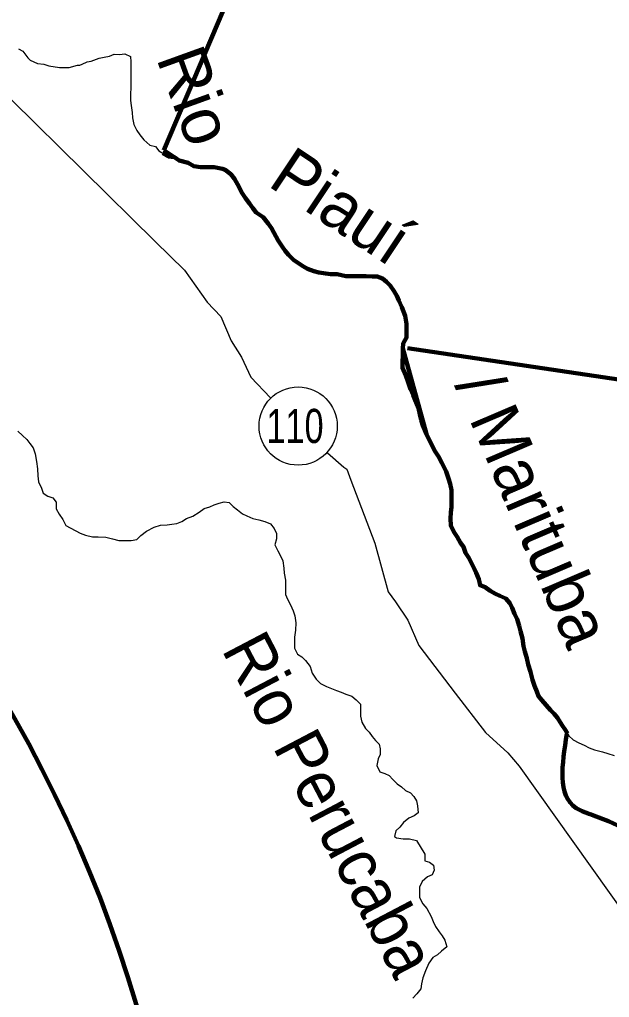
# Model space of a CAD drawing. Extents: x 553962 to 842807, y 8883888 to 9032388.
# Drawn here: x 761992 to 768046, y 8905805 to 8915841 of the extents above; entities that cross this region are included whole.
import ezdxf
from ezdxf.enums import TextEntityAlignment as Align

# ---------------------------------------------------------------- set-up
doc = ezdxf.new("R2010")
doc.units = 0
doc.header["$LTSCALE"] = 20
doc.linetypes.add('MEDIUM_DASHED', pattern=[4.5, 3, -1.5])
for name, color, linetype, lineweight in [('10', 7, 'MEDIUM_DASHED', 60), ('12', 7, 'Continuous', 25), ('24', 7, 'Continuous', 25), ('48', 7, 'Continuous', 25), ('9', 7, 'Continuous', 90)]:
    doc.layers.add(name, color=color, linetype=linetype, lineweight=lineweight)
doc.layers.add('49', color=7, linetype='Continuous')

msp = doc.modelspace()

# ---------------------------------------------------------------- linework, layer by layer
at = {"layer": '10'}
msp.add_open_spline([(780116.15, 8904162.17), (779769.39, 8904177.94), (779422.62, 8904193.71), (779075.85, 8904209.48), (778695.9, 8904226.76), (778318.12, 8904159.82), (777940.98, 8904091.2), (777595.96, 8904028.42), (777262.06, 8903937.23), (776924.32, 8903854.63), (776803.35, 8903825.05), (776686.76, 8903750.37), (776569.67, 8903736.35), (776304.49, 8903704.6), (776099.47, 8903983.3), (775884.02, 8904233.14), (775776.35, 8904358), (775709.21, 8904488.31), (775694.87, 8904611.65), (775670.8, 8904818.6), (776050.43, 8904994.8), (776049.52, 8905226.73), (776047.68, 8905694.49), (775846.84, 8906171.82), (775860.37, 8906646.14), (775878.92, 8907296.23), (776043.6, 8907946.81), (776074.4, 8908597.03), (776108.2, 8909310.28), (775454.34, 8910013.78), (775625.18, 8910702.49), (775746.81, 8911192.83), (776625.71, 8911182.14), (776830.99, 8911648.76), (777030.16, 8912101.51), (777228.07, 8912557.13), (777420.65, 8913014.06), (777556.61, 8913336.63), (777687.59, 8913670.84), (777822.58, 8913983.99), (777919.56, 8914208.95), (778290.17, 8914361.17), (778319.09, 8914551.75), (778353.93, 8914781.35), (778054.25, 8915076.53), (777751.66, 8915261.46), (777515.32, 8915405.89), (777278.58, 8915289.12), (777042.36, 8915285.12), (776916.2, 8915282.98), (776790.12, 8915252.32), (776664.07, 8915261.46), (776484.73, 8915274.46), (776355.68, 8915449.78), (776238.49, 8915592.66), (776104.72, 8915755.73), (776352.41, 8916067), (776214.85, 8916207.73), (776079, 8916346.72), (775768.59, 8916238.74), (775623.77, 8916349.67), (775431.02, 8916497.32), (775387.06, 8916881.69), (775127.26, 8916988.41), (774292.14, 8917331.46), (773439.49, 8917458.06), (772578.86, 8917506.53), (772178.58, 8917529.08), (771773.41, 8917358), (771373.05, 8917411.91), (771257.49, 8917427.47), (771157.31, 8917493.95), (771065.69, 8917577.51), (770748.62, 8917866.67), (770887.06, 8918430.92), (770592.83, 8918689.38), (770430.57, 8918831.91), (770160.08, 8918846.97), (770001.75, 8918996.92), (769746.9, 8919238.26), (769557.21, 8919552.57), (769292.45, 8919801.25), (768866.21, 8920201.59), (768426.67, 8920562.04), (767897.5, 8920818.5), (767600.29, 8920962.53), (767240.04, 8920922.04), (766928.13, 8920842.15), (766587.97, 8920755.03), (766267.79, 8920606.43), (765982.4, 8920369.02), (765805.03, 8920221.47), (765830.93, 8919932.03), (765651.39, 8919801.25), (765249.74, 8919508.69), (764806.41, 8919315.79), (764351.02, 8919115.2), (764017.01, 8918968.08), (763624.43, 8918749.48), (763310.71, 8918831.32)], degree=3, dxfattribs=at)
at = {"layer": '12'}
for points in [[(761912.03, 8915013.75), (763384.05, 8913564.31), (763683.53, 8913268.31), (763916.67, 8912941.85), (764058.77, 8912793.86), (764164.83, 8912544.06), (764271.19, 8912375.76), (764367.23, 8912171.82), (764567.18, 8911957.98)], [(765153.77, 8911394.22), (765321.57, 8911248.03), (765352.06, 8911227.6), (765392.4, 8911115.45), (765639.64, 8910468.05), (765775.35, 8909968.58), (765851.39, 8909866.55)], [(765851.39, 8909866.55), (765978.06, 8909677.84), (766089.18, 8909417.84), (766464.36, 8908928.11), (766773.63, 8908525.11), (767002.1, 8908315.83), (767118.77, 8908178.08), (769146.05, 8905336.93), (769196.75, 8905270.62), (769216.73, 8905163.6), (769289.6, 8904200.68), (769495.6, 8903420.91), (769590.37, 8902870.57), (769609.85, 8902626.02), (769609.02, 8902401.88), (769588.18, 8902274.57), (769536.07, 8901958.83), (769498.71, 8901495.33), (769413.01, 8898973.91), (769458.58, 8898897.42), (769509.37, 8898856.57), (769545.34, 8898826.96)]]:
    msp.add_lwpolyline(points, dxfattribs=at)
at = {"layer": '24'}
for points in [[(761981.19, 8915541.37), (762026.79, 8915515.6), (762075.9, 8915448.89), (762100.99, 8915423.78), (762176.25, 8915390.29)], [(762176.25, 8915390.29), (762243.15, 8915381.92), (762293.32, 8915365.17), (762402.03, 8915348.43), (762502.38, 8915348.43), (762586, 8915373.54), (762611.09, 8915373.54), (762636.17, 8915381.92), (762686.35, 8915407.03), (762728.16, 8915415.4), (762809.57, 8915444.36), (762860.5, 8915454.22), (762916.51, 8915464.05), (762962.43, 8915484.13), (763018.37, 8915483.77), (763074.35, 8915488.51), (763130.12, 8915462.68), (763134.82, 8915406.62), (763134.44, 8915350.59), (763134.05, 8915294.56), (763133.67, 8915238.53), (763133.11, 8915157.03), (763132.44, 8915060.25), (763132.09, 8915009.32), (763136.83, 8914958.35), (763146.51, 8914886.97), (763151.21, 8914830.91), (763166.01, 8914764.59), (763196.11, 8914703.27), (763226.31, 8914657.24), (763266.65, 8914606.04), (763330.23, 8914553.1), (763388.25, 8914539.04), (763422.22, 8914494.49), (763522.56, 8914435.89), (763581.1, 8914427.52), (763631.27, 8914394.03)], [(763631.27, 8914394.03), (763723.26, 8914368.91), (763781.79, 8914335.43), (763848.69, 8914327.05), (763898.86, 8914327.05), (763990.85, 8914327.05), (764074.47, 8914310.31), (764103.76, 8914300.13), (764159.39, 8914253.93), (764199.76, 8914207.83), (764244.94, 8914120.94), (764270.02, 8914069.84), (764310.29, 8914008.46), (764350.59, 8913952.17), (764385.88, 8913906.1), (764421.17, 8913860.02), (764492.05, 8913813.73), (764542.46, 8913747.18), (764577.74, 8913701.11), (764602.86, 8913655.1), (764648.07, 8913573.31), (764688.34, 8913511.93), (764718.54, 8913465.89), (764753.86, 8913424.91), (764804.37, 8913373.65), (764860.07, 8913337.64), (764905.63, 8913306.78), (764946.93, 8913282.3), (765012.12, 8913260.25), (765062.88, 8913244.65), (765134.01, 8913234), (765184.84, 8913228.58), (765250.95, 8913228.16), (765342.36, 8913207.2), (765403.39, 8913206.8), (765464.42, 8913206.41), (765550.89, 8913205.86), (765611.92, 8913205.47), (765662.78, 8913205.14), (765718.58, 8913184.41), (765759.02, 8913148.49), (765794.38, 8913112.61), (765834.68, 8913056.32), (765864.85, 8913005.18), (765884.88, 8912959.21), (765914.9, 8912887.7), (765949.91, 8912800.88), (765964.61, 8912719.29), (765964.01, 8912632.7), (765963.63, 8912576.67), (765927.6, 8912515.77), (765927.18, 8912454.65), (765926.8, 8912398.62), (765921.19, 8912322.25), (765920.8, 8912266.22), (765955.88, 8912189.58), (765980.82, 8912118.11), (766005.76, 8912046.64), (766030.77, 8911985.35), (766050.76, 8911934.28), (766085.8, 8911852.56), (766100.6, 8911786.24), (766115.48, 8911730.11), (766130.35, 8911673.98), (766170.44, 8911587.13)], [(761976.33, 8911618.35), (762021.79, 8911572.22), (762067.28, 8911531.17), (762097.52, 8911490.23), (762132.81, 8911444.16), (762152.73, 8911382.9), (762167.46, 8911306.4), (762177.11, 8911229.93), (762181.7, 8911158.59), (762186.37, 8911097.43), (762216.43, 8911031.02), (762236.42, 8910979.95), (762281.99, 8910949.1), (762332.74, 8910933.49), (762368.03, 8910887.42), (762367.57, 8910821.2), (762397.7, 8910764.98), (762438.01, 8910708.69), (762468.1, 8910647.37), (762615.07, 8910570.02), (762670.87, 8910549.28), (762741.97, 8910533.54), (762797.92, 8910533.19), (762879.26, 8910527.57), (762945.27, 8910511.87), (763011.28, 8910496.16), (763062.14, 8910495.83), (763138.43, 8910495.34), (763194.45, 8910505.17), (763235.42, 8910545.66), (763296.76, 8910591.11), (763373.33, 8910631.37), (763439.59, 8910651.32), (763505.74, 8910655.99), (763556.64, 8910660.76), (763607.57, 8910670.62), (763658.57, 8910690.67), (763704.55, 8910720.94), (763770.84, 8910745.98), (763837.24, 8910786.31), (763888.34, 8910821.64), (763944.43, 8910841.65), (763990.34, 8910861.73), (764041.31, 8910876.69), (764092.27, 8910891.64), (764143.1, 8910886.22), (764183.5, 8910845.21), (764229.03, 8910809.26), (764279.61, 8910768.19), (764325.25, 8910747.52), (764386.1, 8910721.66), (764447.03, 8910705.99), (764507.96, 8910690.31), (764568.81, 8910664.46), (764604.1, 8910618.38), (764629.18, 8910567.28), (764628.79, 8910511.25), (764613.11, 8910450.23), (764643.21, 8910388.91), (764668.32, 8910342.9)], [(766170.44, 8911587.13), (766190.47, 8911541.16), (766215.55, 8911490.06), (766250.66, 8911418.52), (766290.93, 8911357.14), (766326.08, 8911290.69), (766371.25, 8911203.8), (766396.19, 8911132.33), (766411.07, 8911076.2), (766425.87, 8911009.89), (766425.45, 8910948.76), (766425.06, 8910892.73), (766424.71, 8910841.8), (766419.21, 8910780.71), (766413.7, 8910719.62), (766418.3, 8910648.27), (766448.36, 8910581.86), (766483.61, 8910530.7), (766518.79, 8910469.34), (766549.02, 8910428.4), (766568.95, 8910367.14), (766604.2, 8910315.98), (766634.29, 8910254.66), (766659.41, 8910208.65), (766679.44, 8910162.68), (766704.41, 8910096.3), (766719.25, 8910035.08), (766769.97, 8910014.38), (766820.58, 8909978.4), (766876.32, 8909947.48), (766921.95, 8909926.81), (766982.81, 8909900.95), (767023.15, 8909849.75), (767048.26, 8909803.75), (767073.27, 8909742.46), (767098.31, 8909686.27), (767118.2, 8909619.92)], [(764668.32, 8910342.9), (764693.37, 8910286.71), (764703.02, 8910210.24), (764707.75, 8910159.27), (764722.52, 8910087.86), (764722.17, 8910036.93), (764721.5, 8909940.15), (764741.53, 8909894.18), (764771.63, 8909832.86), (764801.72, 8909771.54), (764816.63, 8909720.5), (764826.31, 8909649.13), (764825.79, 8909572.72), (764815.12, 8909501.48), (764814.74, 8909445.45), (764814.35, 8909389.42), (764844.45, 8909328.1), (764890.05, 8909302.34), (764925.37, 8909261.36), (764975.81, 8909199.91), (764995.7, 8909133.56), (765035.96, 8909072.18), (765081.42, 8909026.04)], [(767118.2, 8909619.92), (767133.08, 8909563.79), (767152.89, 8909487.26), (767162.54, 8909410.79), (767177.41, 8909354.66), (767197.3, 8909288.31), (767212.1, 8909222), (767237.01, 8909145.43), (767256.79, 8909063.8), (767276.72, 8909002.55), (767301.76, 8908946.35), (767316.67, 8908895.32), (767351.99, 8908854.34), (767397.41, 8908803.11), (767442.84, 8908751.88), (767478.19, 8908716), (767513.51, 8908675.02), (767558.8, 8908603.41), (767594.01, 8908547.16), (767629.23, 8908490.9), (767674.72, 8908449.86), (767730.46, 8908418.94), (767786.23, 8908393.11), (767836.91, 8908367.31), (767892.72, 8908346.58), (767973.96, 8908325.68), (768029.8, 8908310.04), (768095.77, 8908289.25)], [(765081.42, 8909026.04), (765142.24, 8908995.09), (765192.96, 8908974.39), (765243.68, 8908953.68), (765294.44, 8908938.08), (765340.07, 8908917.41), (765400.96, 8908896.64), (765446.49, 8908860.69), (765491.95, 8908814.56), (765491.56, 8908758.53), (765491.11, 8908692.31), (765505.95, 8908631.09), (765541.09, 8908564.64), (765581.53, 8908528.73), (765611.74, 8908482.69), (765647.06, 8908441.71), (765682.41, 8908405.83), (765692.24, 8908354.83), (765691.85, 8908298.8), (765671.19, 8908253.08), (765660.56, 8908186.93), (765690.62, 8908120.52), (765741.38, 8908104.91), (765787.01, 8908084.24), (765822.33, 8908043.27), (765867.79, 8907997.13), (765913.36, 8907966.27), (765953.8, 8907930.36), (766004.48, 8907904.56), (766039.84, 8907868.68), (766064.95, 8907822.67), (766074.78, 8907771.67), (766084.46, 8907700.3), (766043.56, 8907670), (765987.44, 8907644.89), (765931.18, 8907599.4), (765895.26, 8907553.79), (765854.29, 8907513.3), (765838.65, 8907457.37), (765862.02, 8907442.53)], [(765862.02, 8907442.53), (765930.18, 8907431.33), (765994.11, 8907432.7), (766065.21, 8907416.96), (766150.69, 8907273.79), (766150.24, 8907207.57), (766200.99, 8907191.96), (766241.47, 8907161.14), (766246.21, 8907110.17), (766225.55, 8907064.46), (766179.63, 8907044.38), (766123.34, 8906993.8), (766097.52, 8906937.93), (766097.17, 8906887), (766096.79, 8906830.97), (766131.93, 8906764.52), (766172.31, 8906718.42), (766217.52, 8906636.62), (766237.51, 8906585.56), (766262.59, 8906534.46), (766297.81, 8906478.2), (766328.04, 8906437.26), (766358.24, 8906391.22), (766378.13, 8906324.87), (766321.87, 8906279.39), (766280.94, 8906243.99), (766234.96, 8906213.72), (766193.88, 8906157.95), (766157.72, 8906076.68), (766131.8, 8906005.54), (766116.12, 8905944.51), (766110.69, 8905893.61), (766069.65, 8905842.93), (766028.65, 8905797.35)]]:
    msp.add_lwpolyline(points, dxfattribs=at)
at = {"layer": '48'}
msp.add_circle((764851.33, 8911668.94), 401.28, dxfattribs=at)
at = {"layer": '9'}
for p, q in [((763631.27, 8914394.03), (763472.95, 8914499.71)), ((767609.5, 8908510.77), (767615.52, 8908512.81))]:
    msp.add_line(p, q, dxfattribs=at)
for points in [[(763472.95, 8914499.71), (765229.79, 8918639.75), (764179.45, 8921366.33), (762373.1, 8922620.98), (762522.62, 8923380.92), (762953.67, 8929651.11), (762956.16, 8929646.55)], [(765974.49, 8912469.58), (771548.77, 8911642.28), (776566.81, 8913518.43), (780614.12, 8917160.13), (782189.61, 8916587.3), (785656.16, 8919415.95), (791912.02, 8922868.02)], [(763463.71, 8914470.26), (763522.56, 8914435.89), (763581.1, 8914427.52), (763631.27, 8914394.03)], [(763463.71, 8914470.26), (763522.56, 8914435.89), (763581.1, 8914427.52), (763631.27, 8914394.03)], [(763631.27, 8914394.03), (763723.26, 8914368.91), (763781.79, 8914335.43), (763848.69, 8914327.05), (763898.86, 8914327.05), (763990.85, 8914327.05), (764074.47, 8914310.31), (764103.76, 8914300.13), (764159.39, 8914253.93), (764199.76, 8914207.83), (764244.94, 8914120.94), (764270.02, 8914069.84), (764310.29, 8914008.46), (764350.59, 8913952.17), (764385.88, 8913906.1), (764421.17, 8913860.02), (764492.05, 8913813.73), (764542.46, 8913747.18), (764577.74, 8913701.11), (764602.86, 8913655.1), (764648.07, 8913573.31), (764688.34, 8913511.93), (764718.54, 8913465.89), (764753.86, 8913424.91), (764804.37, 8913373.65), (764860.07, 8913337.64), (764905.63, 8913306.78), (764946.93, 8913282.3), (765012.12, 8913260.25), (765062.88, 8913244.65), (765134.01, 8913234), (765184.84, 8913228.58), (765250.95, 8913228.16), (765342.36, 8913207.2), (765403.39, 8913206.8), (765464.42, 8913206.41), (765550.89, 8913205.86), (765611.92, 8913205.47), (765662.78, 8913205.14), (765718.58, 8913184.41), (765759.02, 8913148.49), (765794.38, 8913112.61), (765834.68, 8913056.32), (765864.85, 8913005.18), (765884.88, 8912959.21), (765914.9, 8912887.7), (765949.91, 8912800.88), (765964.61, 8912719.29), (765964.01, 8912632.7), (765963.63, 8912576.67), (765927.6, 8912515.77), (765927.26, 8912465.57)], [(763631.27, 8914394.03), (763723.26, 8914368.91), (763781.79, 8914335.43), (763848.69, 8914327.05), (763898.86, 8914327.05), (763990.85, 8914327.05), (764074.47, 8914310.31), (764103.76, 8914300.13), (764159.39, 8914253.93), (764199.76, 8914207.83), (764244.94, 8914120.94), (764270.02, 8914069.84), (764310.29, 8914008.46), (764350.59, 8913952.17), (764385.88, 8913906.1), (764421.17, 8913860.02), (764492.05, 8913813.73), (764542.46, 8913747.18), (764577.74, 8913701.11), (764602.86, 8913655.1), (764648.07, 8913573.31), (764688.34, 8913511.93), (764718.54, 8913465.89), (764753.86, 8913424.91), (764804.37, 8913373.65), (764860.07, 8913337.64), (764905.63, 8913306.78), (764946.93, 8913282.3), (765012.12, 8913260.25), (765062.88, 8913244.65), (765134.01, 8913234), (765184.84, 8913228.58), (765250.95, 8913228.16), (765342.36, 8913207.2), (765403.39, 8913206.8), (765464.42, 8913206.41), (765550.89, 8913205.86), (765611.92, 8913205.47), (765662.78, 8913205.14), (765718.58, 8913184.41), (765759.02, 8913148.49), (765794.38, 8913112.61), (765834.68, 8913056.32), (765864.85, 8913005.18), (765884.88, 8912959.21), (765914.9, 8912887.7), (765949.91, 8912800.88), (765964.61, 8912719.29), (765964.01, 8912632.7), (765963.63, 8912576.67), (765927.6, 8912515.77), (765927.26, 8912465.57)], [(765927.26, 8912465.57), (765927.6, 8912515.77), (765963.63, 8912576.67), (765964.01, 8912632.7), (765964.61, 8912719.29), (765949.91, 8912800.88), (765914.9, 8912887.7), (765884.88, 8912959.21), (765864.85, 8913005.18), (765834.68, 8913056.32), (765794.38, 8913112.61), (765759.02, 8913148.49), (765718.58, 8913184.41), (765662.78, 8913205.14), (765611.92, 8913205.47), (765550.89, 8913205.86), (765464.42, 8913206.41), (765403.39, 8913206.8), (765342.36, 8913207.2), (765250.95, 8913228.16), (765184.84, 8913228.58), (765134.01, 8913234), (765062.88, 8913244.65), (765012.12, 8913260.25), (764946.93, 8913282.3), (764905.63, 8913306.78), (764860.07, 8913337.64), (764804.37, 8913373.65), (764753.86, 8913424.91), (764718.54, 8913465.89), (764688.34, 8913511.93), (764648.07, 8913573.31), (764602.86, 8913655.1), (764577.74, 8913701.11), (764542.46, 8913747.18), (764492.05, 8913813.73), (764421.17, 8913860.02), (764385.88, 8913906.1), (764350.59, 8913952.17), (764310.29, 8914008.46), (764270.02, 8914069.84), (764244.94, 8914120.94), (764199.76, 8914207.83), (764159.39, 8914253.93), (764103.76, 8914300.13), (764074.47, 8914310.31), (763990.85, 8914327.05), (763898.86, 8914327.05), (763848.69, 8914327.05), (763781.79, 8914335.43), (763723.26, 8914368.91), (763631.27, 8914394.03)], [(765927.26, 8912465.57), (765927.18, 8912454.65), (765926.8, 8912398.62), (765921.19, 8912322.25), (765920.8, 8912266.22), (765955.88, 8912189.58), (765980.82, 8912118.11), (766005.76, 8912046.64), (766030.77, 8911985.35), (766050.76, 8911934.28), (766085.8, 8911852.56), (766100.6, 8911786.24), (766115.48, 8911730.11), (766130.35, 8911673.98), (766170.44, 8911587.13)], [(765927.26, 8912465.57), (765927.18, 8912454.65), (765926.8, 8912398.62), (765921.19, 8912322.25), (765920.8, 8912266.22), (765955.88, 8912189.58), (765980.82, 8912118.11), (766005.76, 8912046.64), (766030.77, 8911985.35), (766050.76, 8911934.28), (766085.8, 8911852.56), (766100.6, 8911786.24), (766115.48, 8911730.11), (766130.35, 8911673.98), (766170.44, 8911587.13)], [(767118.2, 8909619.92), (767098.31, 8909686.27), (767073.27, 8909742.46), (767048.26, 8909803.75), (767023.15, 8909849.75), (766982.81, 8909900.95), (766921.95, 8909926.81), (766876.32, 8909947.48), (766820.58, 8909978.4), (766769.97, 8910014.38), (766719.25, 8910035.08), (766704.41, 8910096.3), (766679.44, 8910162.68), (766659.41, 8910208.65), (766634.29, 8910254.66), (766604.2, 8910315.98), (766568.95, 8910367.14), (766549.02, 8910428.4), (766518.79, 8910469.34), (766483.61, 8910530.7), (766448.36, 8910581.86), (766418.3, 8910648.27), (766413.7, 8910719.62), (766419.21, 8910780.71), (766424.71, 8910841.8), (766425.06, 8910892.73), (766425.45, 8910948.76), (766425.87, 8911009.89), (766411.07, 8911076.2), (766396.19, 8911132.33), (766371.25, 8911203.8), (766326.08, 8911290.69), (766290.93, 8911357.14), (766250.66, 8911418.52), (766215.55, 8911490.06), (766190.47, 8911541.16), (766170.44, 8911587.13), (765927.26, 8912465.57)], [(766170.44, 8911587.13), (766190.47, 8911541.16), (766215.55, 8911490.06), (766250.66, 8911418.52), (766290.93, 8911357.14), (766326.08, 8911290.69), (766371.25, 8911203.8), (766396.19, 8911132.33), (766411.07, 8911076.2), (766425.87, 8911009.89), (766425.45, 8910948.76), (766425.06, 8910892.73), (766424.71, 8910841.8), (766419.21, 8910780.71), (766413.7, 8910719.62), (766418.3, 8910648.27), (766448.36, 8910581.86), (766483.61, 8910530.7), (766518.79, 8910469.34), (766549.02, 8910428.4), (766568.95, 8910367.14), (766604.2, 8910315.98), (766634.29, 8910254.66), (766659.41, 8910208.65), (766679.44, 8910162.68), (766704.41, 8910096.3), (766719.25, 8910035.08), (766769.97, 8910014.38), (766820.58, 8909978.4), (766876.32, 8909947.48), (766921.95, 8909926.81), (766982.81, 8909900.95), (767023.15, 8909849.75), (767048.26, 8909803.75), (767073.27, 8909742.46), (767098.31, 8909686.27), (767118.2, 8909619.92)], [(766170.44, 8911587.13), (766190.47, 8911541.16), (766215.55, 8911490.06), (766250.66, 8911418.52), (766290.93, 8911357.14), (766326.08, 8911290.69), (766371.25, 8911203.8), (766396.19, 8911132.33), (766411.07, 8911076.2), (766425.87, 8911009.89), (766425.45, 8910948.76), (766425.06, 8910892.73), (766424.71, 8910841.8), (766419.21, 8910780.71), (766413.7, 8910719.62), (766418.3, 8910648.27), (766448.36, 8910581.86), (766483.61, 8910530.7), (766518.79, 8910469.34), (766549.02, 8910428.4), (766568.95, 8910367.14), (766604.2, 8910315.98), (766634.29, 8910254.66), (766659.41, 8910208.65), (766679.44, 8910162.68), (766704.41, 8910096.3), (766719.25, 8910035.08), (766769.97, 8910014.38), (766820.58, 8909978.4), (766876.32, 8909947.48), (766921.95, 8909926.81), (766982.81, 8909900.95), (767023.15, 8909849.75), (767048.26, 8909803.75), (767073.27, 8909742.46), (767098.31, 8909686.27), (767118.2, 8909619.92)], [(767118.2, 8909619.92), (767133.08, 8909563.79), (767152.89, 8909487.26), (767162.54, 8909410.79), (767177.41, 8909354.66), (767197.3, 8909288.31), (767212.1, 8909222), (767237.01, 8909145.43), (767256.79, 8909063.8), (767276.72, 8909002.55), (767301.76, 8908946.35), (767316.67, 8908895.32), (767351.99, 8908854.34), (767397.41, 8908803.11), (767442.84, 8908751.88), (767478.19, 8908716), (767513.51, 8908675.02), (767558.8, 8908603.41), (767594.01, 8908547.16), (767615.52, 8908512.81)], [(767118.2, 8909619.92), (767133.08, 8909563.79), (767152.89, 8909487.26), (767162.54, 8909410.79), (767177.41, 8909354.66), (767197.3, 8909288.31), (767212.1, 8909222), (767237.01, 8909145.43), (767256.79, 8909063.8), (767276.72, 8909002.55), (767301.76, 8908946.35), (767316.67, 8908895.32), (767351.99, 8908854.34), (767397.41, 8908803.11), (767442.84, 8908751.88), (767478.19, 8908716), (767513.51, 8908675.02), (767558.8, 8908603.41), (767594.01, 8908547.16), (767615.52, 8908512.81)], [(767615.52, 8908512.81), (767594.01, 8908547.16), (767558.8, 8908603.41), (767513.51, 8908675.02), (767478.19, 8908716), (767442.84, 8908751.88), (767397.41, 8908803.11), (767351.99, 8908854.34), (767316.67, 8908895.32), (767301.76, 8908946.35), (767276.72, 8909002.55), (767256.79, 8909063.8), (767237.01, 8909145.43), (767212.1, 8909222), (767197.3, 8909288.31), (767177.41, 8909354.66), (767162.54, 8909410.79), (767152.89, 8909487.26), (767133.08, 8909563.79), (767118.2, 8909619.92)]]:
    msp.add_lwpolyline(points, dxfattribs=at)
for points in [[(752845.84, 8918517.4), (763638.29, 8902563.49), (763638.29, 8902563.48)], [(767609.5, 8908510.77), (767705.4, 8907748.75), (767883.32, 8907673.87), (770082.67, 8903005.66)], [(770082.67, 8903005.66), (767883.32, 8907673.87), (767705.4, 8907748.75), (767609.5, 8908510.77)]]:
    msp.add_spline(points, degree=3, dxfattribs=at)

# ---------------------------------------------------------------- texts
at = {"layer": '48', "width": 0.75}
msp.add_text('110', height=350, dxfattribs=at).set_placement((764819.7, 8911495.59), align=Align.CENTER)
at = {"layer": '49'}
for s, rotation, p in [('Rio', 289.863, (763563.06, 8914973.97)), ('Piauí', 326.297, (765160.65, 8913719.28)), ('/ Marituba', 293.11, (767039.85, 8910721.1))]:
    msp.add_text(s, height=500, rotation=rotation, dxfattribs=at).set_placement(p, align=Align.CENTER)
at = {"layer": '49', "width": 0.95}
msp.add_text('Rio Perucaba', height=500, rotation=297.707, dxfattribs=at).set_placement((764955.43, 8907672.4), align=Align.CENTER)

doc.saveas('drawing.dxf')
